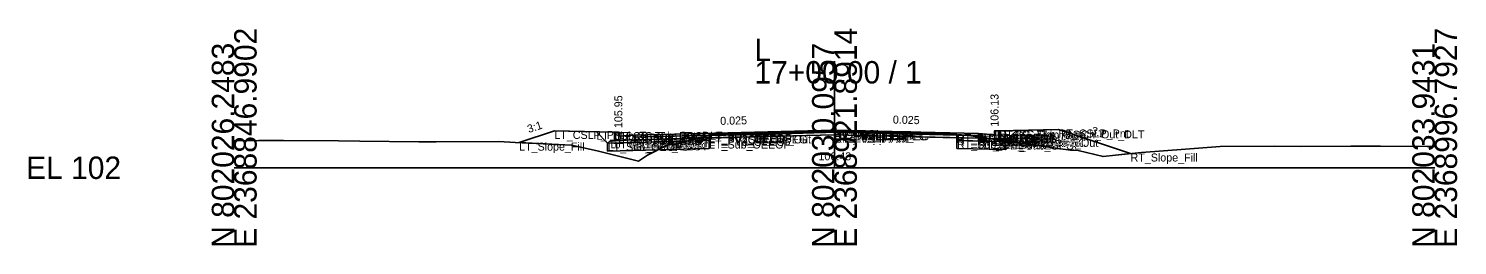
# Model space of a CAD drawing. Extents: x -26 to 8153, y -10 to 9520.
# Drawn here: x -25.7 to 152.8, y 7990.3 to 8017.4 of the extents above; entities that cross this region are included whole.
import ezdxf

# ---------------------------------------------------------------- set-up
doc = ezdxf.new("R2010")
doc.units = 0
for name, color, linetype in [('Exist CMT Pavement', 7, 'Continuous'), ('Exist Cross Section Cell', 7, 'Continuous'), ('Exist XS Center Line Elevation Label', 7, 'Continuous'), ('Exist XS Ground Line', 7, 'Continuous'), ('Prop CMT Conc Surface', 7, 'Continuous'), ('Prop CMT Concrete Structures', 7, 'Continuous'), ('Prop CMT Pvmt Course 1', 7, 'Continuous'), ('Prop CMT Pvmt Course 1 CG', 7, 'Continuous'), ('Prop CMT Pvmt Course 1 Wedge', 7, 'Continuous'), ('Prop CMT Pvmt Course 2', 7, 'Continuous'), ('Prop CMT Pvmt Course 2 Wedge', 7, 'Continuous'), ('Prop CMT Pvmt Course 3', 7, 'Continuous'), ('Prop CMT Pvmt Course 3 Wedge', 7, 'Continuous'), ('Prop CMT Pvmt Surface', 7, 'Continuous'), ('Prop CMT Pvmt Wedge Surface 1', 7, 'Continuous'), ('Prop CMT Pvmt Wedge Surface 2', 7, 'Continuous'), ('Prop CMT Pvmt Wedge Surface 3', 7, 'Continuous'), ('Prop CMT Shallow Undercut', 7, 'Continuous'), ('Prop CMT Shallow Undercut Boundary', 7, 'Continuous'), ('Prop CMT Slope Grass', 7, 'Continuous'), ('Prop CMT Subgrade Earthwork', 7, 'Continuous'), ('Prop XS Earthwork Shape', 7, 'Continuous'), ('Prop XS Hydro Elevations', 7, 'Continuous'), ('Prop XS SE Text', 7, 'Continuous'), ('Prop XS Side Slope Text', 7, 'Continuous'), ('Prop XS Subgrade Earthwork', 7, 'Continuous'), ('Scratch_Level_2', 7, 'Continuous'), ('Scratch_Level_6', 7, 'Continuous')]:
    doc.layers.add(name, color=color, linetype=linetype)

msp = doc.modelspace()

# ---------------------------------------------------------------- linework, layer by layer
at = {"layer": 'Exist CMT Pavement'}
for p, q in [((59.34, 8004.04), (65.6, 8004.15)), ((65.6, 8004.15), (75.21, 8004.44)), ((75.21, 8004.44), (81.78, 8004.3)), ((81.78, 8004.3), (91.52, 8004.05))]:
    msp.add_line(p, q, dxfattribs=at)
at = {"layer": 'Exist Cross Section Cell'}
for p, q in [((75, 8000), (75, 8013.32)), ((0, 8000), (75, 8000)), ((75, 8000), (150, 8000))]:
    msp.add_line(p, q, dxfattribs=at)
at = {"layer": 'Exist XS Ground Line'}
for p, q in [((55.47, 8003.05), (59.34, 8004.04)), ((59.34, 8004.04), (65.6, 8004.15)), ((65.6, 8004.15), (75.21, 8004.44)), ((75.21, 8004.44), (81.78, 8004.3)), ((81.78, 8004.3), (91.52, 8004.05)), ((91.52, 8004.05), (103.3, 8002.36)), ((0, 8003.38), (3.04, 8003.42)), ((3.04, 8003.42), (6.17, 8003.41)), ((6.17, 8003.41), (13.05, 8003.37)), ((13.05, 8003.37), (15.7, 8003.32)), ((15.7, 8003.32), (23.07, 8003.24)), ((23.07, 8003.24), (25.22, 8003.25)), ((25.22, 8003.25), (33.08, 8003.26)), ((33.08, 8003.26), (35.12, 8003.16)), ((35.12, 8003.16), (42.13, 8002.81)), ((42.13, 8002.81), (45.35, 8002.13)), ((45.35, 8002.13), (50.5, 8000.83)), ((51.63, 8001.57), (54.1, 8002.83)), ((54.1, 8002.83), (55.47, 8003.05)), ((103.3, 8002.36), (104.5, 8002.21)), ((104.5, 8002.21), (104.91, 8002.19)), ((104.91, 8002.19), (105.45, 8002.14)), ((105.45, 8002.14), (108.57, 8001.39)), ((110.1, 8001.58), (113.38, 8001.91)), ((113.38, 8001.91), (118.87, 8002.31)), ((118.87, 8002.31), (123.2, 8002.66)), ((123.2, 8002.66), (129.99, 8002.69)), ((129.99, 8002.69), (133.22, 8002.67)), ((133.22, 8002.67), (139.51, 8002.7)), ((139.51, 8002.7), (143.23, 8002.7)), ((143.23, 8002.7), (149.04, 8002.67)), ((149.04, 8002.67), (150, 8002.65)), ((50.5, 8000.83), (51.63, 8001.57)), ((108.57, 8001.39), (110.1, 8001.58))]:
    msp.add_line(p, q, dxfattribs=at)
at = {"layer": 'Prop CMT Conc Surface'}
for points in [[(48, 8003.95), (48, 8004.45), (47.5, 8004.45)], [(50, 8004.08), (48, 8003.95)], [(93, 8004.26), (95, 8004.13)], [(95, 8004.13), (95, 8004.63), (95.5, 8004.63)]]:
    msp.add_lwpolyline(points, dxfattribs=at)
at = {"layer": 'Prop CMT Concrete Structures'}
for points in [[(50, 8004.08), (48, 8003.95), (48, 8004.45), (47.5, 8004.45)], [(47.5, 8004.45), (47.5, 8003.44), (50, 8003.5)], [(50, 8003.5), (50, 8004.08)], [(93, 8004.26), (95, 8004.13), (95, 8004.63), (95.5, 8004.63)], [(95.5, 8004.63), (95.5, 8003.61), (93, 8003.67)], [(93, 8003.67), (93, 8004.26)]]:
    msp.add_lwpolyline(points, dxfattribs=at)
at = {"layer": 'Prop CMT Pvmt Course 1'}
for points in [[(75, 8004.71), (50, 8004.08)], [(50, 8004.08), (50, 8003.83)], [(50, 8003.83), (59.34, 8004.07)], [(59.34, 8004.19), (75, 8004.58)], [(59.34, 8004.07), (59.34, 8004.19)], [(75, 8004.46), (75, 8004.71)], [(75, 8004.71), (93, 8004.26)], [(75, 8004.46), (75, 8004.71)], [(75, 8004.58), (75, 8004.46), (75, 8004.46)], [(90.31, 8004.2), (75, 8004.58)], [(75, 8004.58), (75, 8004.46), (75, 8004.46)], [(90.31, 8004.07), (90.31, 8004.2)], [(93, 8004.01), (90.31, 8004.07)], [(93, 8004.26), (93, 8004.01)]]:
    msp.add_lwpolyline(points, dxfattribs=at)
at = {"layer": 'Prop CMT Pvmt Course 1 CG'}
for points in [[(93, 8003.67), (96, 8003.6), (96.34, 8003.26)], [(93, 8003.34), (93, 8003.67)], [(50, 8003.5), (47, 8003.42), (46.66, 8003.09)], [(46.66, 8003.09), (50, 8003.17)], [(50, 8003.17), (50, 8003.5)], [(96.34, 8003.26), (93, 8003.34)]]:
    msp.add_lwpolyline(points, dxfattribs=at)
at = {"layer": 'Prop CMT Pvmt Course 1 Wedge'}
for points in [[(75, 8004.58), (59.34, 8004.19)], [(75, 8004.58), (90.31, 8004.2)]]:
    msp.add_lwpolyline(points, dxfattribs=at)
at = {"layer": 'Prop CMT Pvmt Course 2'}
for points in [[(59.34, 8004.07), (50, 8003.83)], [(50, 8003.83), (50, 8003.5)], [(50, 8003.5), (59.34, 8003.74)], [(59.34, 8003.74), (59.34, 8004.07)], [(90.31, 8003.74), (90.31, 8004.07)], [(90.31, 8004.07), (93, 8004.01)], [(93, 8003.68), (90.31, 8003.74)], [(93, 8004.01), (93, 8003.68)]]:
    msp.add_lwpolyline(points, dxfattribs=at)
at = {"layer": 'Prop CMT Pvmt Course 2 Wedge'}
for points in [[(75, 8004.46), (59.34, 8004.07)], [(75, 8004.46), (90.31, 8004.07)]]:
    msp.add_lwpolyline(points, dxfattribs=at)
at = {"layer": 'Prop CMT Pvmt Course 3'}
for points in [[(59.34, 8003.74), (50, 8003.5)], [(59.34, 8003.4), (59.34, 8003.74)], [(90.31, 8003.74), (93, 8003.68)], [(90.31, 8003.41), (90.31, 8003.74)], [(93, 8003.68), (93, 8003.34)], [(50, 8003.5), (50, 8003.17)], [(50, 8003.17), (59.34, 8003.4)], [(93, 8003.34), (90.31, 8003.41)]]:
    msp.add_lwpolyline(points, dxfattribs=at)
at = {"layer": 'Prop CMT Pvmt Course 3 Wedge'}
for points in [[(75, 8004.13), (59.34, 8003.74)], [(75, 8004.13), (90.31, 8003.74)]]:
    msp.add_lwpolyline(points, dxfattribs=at)
at = {"layer": 'Prop CMT Pvmt Surface'}
for points in [[(75, 8004.71), (50, 8004.08)], [(75, 8004.71), (93, 8004.26)]]:
    msp.add_lwpolyline(points, dxfattribs=at)
at = {"layer": 'Prop CMT Pvmt Wedge Surface 1'}
for points in [[(50, 8003.83), (50, 8004.08)], [(59.34, 8004.07), (50, 8003.83)], [(75, 8004.58), (59.34, 8004.19)], [(59.34, 8004.19), (59.34, 8004.07)], [(75, 8004.58), (90.31, 8004.2)], [(90.31, 8004.2), (90.31, 8004.07)], [(90.31, 8004.07), (93, 8004.01)], [(93, 8004.01), (93, 8004.26)]]:
    msp.add_lwpolyline(points, dxfattribs=at)
at = {"layer": 'Prop CMT Pvmt Wedge Surface 2'}
for points in [[(75, 8004.46), (50, 8003.83)], [(50, 8003.83), (50, 8004.08)], [(75, 8004.46), (93, 8004.01)], [(93, 8004.01), (93, 8004.26)]]:
    msp.add_lwpolyline(points, dxfattribs=at)
at = {"layer": 'Prop CMT Pvmt Wedge Surface 3'}
for points in [[(75, 8004.13), (50, 8003.5)], [(50, 8003.5), (50, 8004.08)], [(75, 8004.13), (93, 8003.68)], [(93, 8003.68), (93, 8004.26)]]:
    msp.add_lwpolyline(points, dxfattribs=at)
at = {"layer": 'Prop CMT Shallow Undercut'}
for p, q in [((90.31, 8003.41), (90.31, 8002.41)), ((96.34, 8003.26), (90.31, 8003.41)), ((90.31, 8002.41), (96.34, 8002.26)), ((96.34, 8002.26), (96.34, 8003.26))]:
    msp.add_line(p, q, dxfattribs=at)
msp.add_lwpolyline([(59.34, 8003.4), (59.34, 8002.4), (52.94, 8002.24), (54.1, 8002.83), (55.47, 8003.05), (56.57, 8003.33)], close=True, dxfattribs=at)
at = {"layer": 'Prop CMT Shallow Undercut Boundary'}
for p, q in [((46.66, 8003.09), (59.34, 8003.4)), ((46.66, 8003.09), (46.66, 8002.09)), ((46.66, 8002.09), (59.34, 8002.4)), ((59.34, 8003.4), (59.34, 8002.4)), ((90.31, 8003.41), (90.31, 8002.41)), ((90.31, 8003.41), (96.34, 8003.26)), ((90.31, 8002.41), (96.34, 8002.26)), ((96.34, 8003.26), (96.34, 8002.26))]:
    msp.add_line(p, q, dxfattribs=at)
at = {"layer": 'Prop CMT Slope Grass'}
for points in [[(47.5, 8004.45), (40, 8004.6), (35.6, 8003.14)], [(95.5, 8004.63), (103, 8004.78), (112, 8001.78)]]:
    msp.add_lwpolyline(points, dxfattribs=at)
at = {"layer": 'Prop CMT Subgrade Earthwork'}
for points in [[(50, 8003.17), (46.66, 8003.09), (45.25, 8004.5)], [(59.34, 8003.4), (59.36, 8004.04)], [(90.31, 8003.41), (90.31, 8004.08)], [(93, 8003.34), (96.34, 8003.26), (97.75, 8004.67)], [(59.34, 8003.4), (50, 8003.17)], [(90.31, 8003.41), (93, 8003.34)]]:
    msp.add_lwpolyline(points, dxfattribs=at)
at = {"layer": 'Prop XS Earthwork Shape'}
for points in [[(45.35, 8002.13), (50.5, 8000.83), (51.63, 8001.57), (52.94, 8002.24), (46.66, 8002.09), (46.66, 8003.09), (45.25, 8004.5), (40, 8004.6), (35.6, 8003.14), (42.13, 8002.81)], [(59.34, 8003.4), (59.36, 8004.04), (59.34, 8004.04), (56.57, 8003.33)], [(90.31, 8003.41), (93, 8003.34), (96.34, 8003.26), (96.42, 8003.34), (91.52, 8004.05), (90.31, 8004.08)], [(97.75, 8004.67), (103, 8004.78), (112, 8001.78), (110.1, 8001.58), (108.57, 8001.39), (105.45, 8002.14), (104.91, 8002.19), (104.5, 8002.21), (103.3, 8002.36), (96.42, 8003.34)], [(54.1, 8002.83), (55.47, 8003.05), (56.57, 8003.33), (50, 8003.17), (46.66, 8003.09), (46.66, 8002.09), (52.94, 8002.24)], [(54.1, 8002.83), (55.47, 8003.05), (56.57, 8003.33), (59.34, 8003.4), (59.34, 8002.4), (52.94, 8002.24)], [(90.31, 8003.41), (93, 8003.34), (96.34, 8003.26), (96.34, 8002.26), (90.31, 8002.41)]]:
    msp.add_lwpolyline(points, close=True, dxfattribs=at)
at = {"layer": 'Prop XS Subgrade Earthwork'}
for p, q in [((46.66, 8003.09), (59.34, 8003.4)), ((90.31, 8003.41), (96.34, 8003.26))]:
    msp.add_line(p, q, dxfattribs=at)
at = {"layer": 'Scratch_Level_6'}
for p, q in [((90.31, 8003.41), (90.31, 8002.41)), ((96.34, 8003.26), (90.31, 8003.41)), ((90.31, 8002.41), (96.34, 8002.26)), ((96.34, 8002.26), (96.34, 8003.26))]:
    msp.add_line(p, q, dxfattribs=at)
msp.add_lwpolyline([(59.34, 8003.4), (59.34, 8002.4), (52.94, 8002.24), (54.1, 8002.83), (55.47, 8003.05), (56.57, 8003.33)], close=True, dxfattribs=at)

# ---------------------------------------------------------------- texts
at = {"layer": 'Exist Cross Section Cell'}
for s, p in [('E 2368846.9902', (2.8, 7990)), ('E 2368921.8914', (77.8, 7990)), ('E 2368996.7927', (152.8, 7990)), ('N 802026.2483', (0, 7990)), ('N 802030.0957', (75, 7990)), ('N 802033.9431', (150, 7990))]:
    msp.add_text(s, height=2.8, rotation=90, dxfattribs=at).set_placement(p)
for s, p in [('L', (65, 8013.32)), ('17+00.00 / 1', (65, 8010.52)), ('EL 102', (-26, 7998.6))]:
    msp.add_text(s, height=2.8, dxfattribs=at).set_placement(p)
at = {"layer": 'Exist XS Center Line Elevation Label'}
msp.add_text('106.43', height=1, dxfattribs=at).set_placement((73, 8000.93))
at = {"layer": 'Prop XS Hydro Elevations'}
for s, p in [('105.95', (48.5, 8004.95)), ('106.13', (95.5, 8005.13))]:
    msp.add_text(s, height=1, rotation=90, dxfattribs=at).set_placement(p)
at = {"layer": 'Prop XS SE Text'}
for rotation, p in [(1.4321, (60.74, 8005.35)), (358.5679, (82.29, 8005.52))]:
    msp.add_text('0.025', height=1, rotation=rotation, dxfattribs=at).set_placement(p)
at = {"layer": 'Prop XS Side Slope Text'}
for rotation, p in [(18.4349, (36.81, 8004.33)), (341.5651, (106.99, 8004.24))]:
    msp.add_text('3:1', height=1, rotation=rotation, dxfattribs=at).set_placement(p)
at = {"layer": 'Scratch_Level_2'}
for s, p in [('LT_CSLP_Pnt', (40, 8003.6)), ('LT_Sub_Trench_Out_DLT', (45.25, 8003.5)), ('LT_CG_Top_BOC', (47.5, 8003.45)), ('LT_CG_Top_Face', (48, 8003.45)), ('LT_CG_Top_Gut', (48, 8002.95)), ('LT_PV1_OEOT', (50, 8003.08)), ('LT_PV2_OEOT', (50, 8002.83)), ('LT_PV1_OEEOP', (59.34, 8003.19)), ('LT_PV2_OEEOP', (59.34, 8003.07)), ('LT_PV_OEEOP_EG', (59.34, 8003.04)), ('LT_PV3_OEEOP', (59.34, 8002.74)), ('LT_PV_Sub_Tie_Out', (59.36, 8003.04)), ('PV1_PGL', (75, 8003.71)), ('RT_PV1_IEEOP', (75, 8003.58)), ('LT_PV1_IEEOP', (75, 8003.58)), ('RT_PV2_IEEOP', (75, 8003.46)), ('LT_PV2_IEEOP', (75, 8003.46)), ('PV2_PGL', (75, 8003.46)), ('RT_PV_IEEOP_EG', (75, 8003.43)), ('LT_PV_IEEOP_EG', (75, 8003.43)), ('RT_PV3_IEEOP', (75, 8003.13)), ('LT_PV3_IEEOP', (75, 8003.13)), ('RT_PV_Sub_Tie_Out', (90.29, 8003.08)), ('RT_PV1_OEEOP', (90.31, 8003.2)), ('RT_PV_OEEOP_EG', (90.31, 8003.08)), ('RT_PV2_OEEOP', (90.31, 8003.07)), ('RT_PV3_OEEOP', (90.31, 8002.74)), ('RT_PV1_OEOT', (93, 8003.26)), ('RT_PV2_OEOT', (93, 8003.01)), ('RT_PV3_OEOT', (93, 8002.68)), ('RT_CG_Bot_IE', (93, 8002.67)), ('RT_CG_Top_Face', (95, 8003.63)), ('RT_CG_Top_Gut', (95, 8003.13)), ('RT_CG_Top_BOC', (95.5, 8003.63)), ('RT_CG_Bot_BOC', (95.5, 8002.61)), ('RT_CG1_Shelf_Out', (96, 8002.6)), ('RT_Sub_Trench_Out_DLT', (97.75, 8003.67)), ('RT_CSLP_Pnt', (103, 8003.78)), ('LT_Slope_Fill', (35.6, 8002.14)), ('LT_Sub_OEOP', (46.66, 8002.09)), ('LT_CG1_Shelf_Out', (47, 8002.42)), ('LT_CG_Bot_BOC', (47.5, 8002.44)), ('LT_PV3_OEOT', (50, 8002.5)), ('LT_CG_Bot_IE', (50, 8002.5)), ('LT_Sub_OEOT', (50, 8002.17)), ('LT_Sub_OEEOP', (59.34, 8002.4)), ('RT_Sub_OEEOP', (90.31, 8002.41)), ('RT_Sub_OEOT', (93, 8002.34)), ('RT_Sub_OEOP', (96.34, 8002.26)), ('RT_Slope_Fill', (112, 8000.78))]:
    msp.add_text(s, height=1, dxfattribs=at).set_placement(p)

doc.saveas('drawing.dxf')
